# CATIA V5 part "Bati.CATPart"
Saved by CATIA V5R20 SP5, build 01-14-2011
Part number: Bati
Bounding box of the stored display mesh (mm): x -250 to 20, y -10 to 10, z -15 to 130
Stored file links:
  D:\thinkmotion-MPB\Dropbox\IAO\IAO_2010\iao\IAO OK\IAO_2010_1447_melguidj\Catia_1447_melguidj\Bati.CATPart
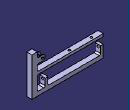
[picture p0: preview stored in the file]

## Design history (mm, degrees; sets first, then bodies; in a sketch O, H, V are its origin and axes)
Body1 (main body)
  Plane1: stored without definition
  Sketch1 on zx-plane, origin (0, 0, 0), H (-1, 0, 0), V (0, 0, 1)
    line L1 (0, 130) -> (-20, 130)
    point P1 (0, 130)
    line L2 (-20, 130) -> (-20, -15)
    line L3 (-20, -15) -> (250, -15)
    point P4 (250, -15)
    line L4 (0, 130) -> (0, 115)
    line L5 (5, 0) -> (25, 0)
    line L6 (30, 5) -> (30, 30)
    line L7 (30, 30) -> (40, 30)
    line L8 (40, 30) -> (40, 5)
    point P7 (40, 0)
    line L9 (45, 0) -> (235, 0)
    line L10 (240, 5) -> (240, 30)
    point P8 (240, 30)
    line L11 (240, 30) -> (250, 30)
    line L12 (250, 30) -> (250, -15)
    point P10 (250, -15)
    reference intersected line E1 through (0, 0) direction (-1, 0) from Plane1
    point P11 (0, 110)
    line L13 (5, 110) -> (20, 110)
    line L14 (20, 90) -> (5, 90)
    line L15 (0, 85) -> (0, 70)
    circle A1 centre (20, 100) radius 4
    point P12 (20, 100)
    arc A2 centre (45, 5) radius 5 from (40, 5) to (45, 0) ccw
    arc A3 centre (25, 5) radius 5 from (30, 5) to (25, 0) cw
    arc A4 centre (5, 5) radius 5 from (5, 0) to (0, 5) cw
    arc A5 centre (235, 5) radius 5 from (240, 5) to (235, 0) cw
    arc A6 centre (5, 85) radius 5 from (5, 90) to (0, 85) ccw
    arc A7 centre (5, 115) radius 5 from (5, 110) to (0, 115) cw
    line L16 (5, 65) -> (250, 65)
    line L17 (250, 65) -> (250, 55)
    line L18 (250, 55) -> (5, 55)
    line L19 (0, 50) -> (0, 5)
    arc A8 centre (5, 50) radius 5 from (0, 50) to (5, 55) cw
    arc A9 centre (5, 70) radius 5 from (5, 65) to (0, 70) cw
    arc A10 centre (20, 100) radius 10 from (20, 90) to (20, 110) ccw
    distance L9 L3 = 15
    distance L10 L12 = 10
    length L7 = 10
    distance L8 L10 = 200
    distance L6 L4 = 30
    length L1 = 20
    distance L1 E1 = 130
    distance L14 L5 = 90
    distance P12 L13 = 10
    radius A1 = 4
    distance L7 L9 = 30
    radius A2 = 5
    radius A3 = 5
    radius A4 = 5
    radius A5 = 5
    radius A6 = 5
    radius A7 = 5
    length L17 = 10
    distance L18 L5 = 55
    radius A8 = 5
    radius A9 = 5
    distance P12 L4 = 20
    coincidence: P1 V, P7 L5, P8 L7, P10 P4, L5 H, L4 L15, L8 P7, L9 P7, L13 P11, L4 P11, L17 L12, L15 L19
    horizontal: L1 H, L3 H, L5 H, L7 H, L9 H, L11 H, L13 H, L14 H, L16 H, L18 H
    vertical: L2 V, L4 V, L6 V, L8 V, L10 V, L12 V, L15 V, L17 V, L19 V
    tangency: A2 L8, A2 L9, A3 L6, A3 L5, A4 L5, A4 L15, A5 L10, A5 L9, A6 L14, A6 L15, A7 L13, A7 L4, A8 L19, A8 L18, A9 L16, A9 L15, A10 L13, A10 L14
  Pad1: profile Sketch1, direction (0, 1, 0), length 10, mirrored extent
  Sketch2 on face of Pad1 from Sketch1.L12, origin (-250, 0, 0), H (0, -1, 0), V (0, 0, 1)
    circle A1 centre (0, 23) radius 4
    point P1 (0, 23)
    reference projected line E1 (10, 30) -> (-10, 30) from edge [face of Pad1 from Sketch1.L11 | face of Pad1 from Sketch1.L12]
    radius A1 = 4
    distance E1 P1 = 7
    coincidence: P1 V
  Pocket1: profile Sketch2, direction (1, 0, 0), up to face of Pad1 from Sketch1.L6
  Sketch3 on face of Pad1 from Sketch1.L13, origin (0, 0, 110), H (1, 0, 0), V (0, 1, 0)
    line L1 (-53.7186, 7) -> (-5, 7)
    line L2 (-5, 7) -> (-5, -7)
    line L3 (-5, -7) -> (-53.7186, -7)
    line L4 (-53.7186, -7) -> (-53.7186, 7)
    reference projected line E1 (-20, 10) -> (-5, 10) from edge [face of Pad1 from Sketch1.L13 | end face of Pad1]
    reference projected line E2 (-20, -10) -> (-5, -10) from edge [start face of Pad1 | face of Pad1 from Sketch1.L13]
    reference projected line E3 (-5, -10) -> (-5, 10) from edge [face of Pad1 from Sketch1.A7 | face of Pad1 from Sketch1.L13]
    distance L1 E1 = 3
    distance L3 E2 = 3
    horizontal: L1 H, L3 H
    vertical: L2 V, L4 V
    coincidence: L2 E3
  Pocket2: profile Sketch3, direction (0, 0, -1), up to face of Pad1 from Sketch1.L14
  Sketch4 on face of Pad1 from Sketch1.L16, origin (0, 0, 65), H (1, 0, 0), V (0, 1, 0)
    circle A1 centre (-215, 0) radius 4
    point P1 (-215, 0)
    reference projected line E1 (-250, -10) -> (-250, 10) from edge [face of Pad1 from Sketch1.L16 | face of Pad1 from Sketch1.L17]
    radius A1 = 4
    distance P1 E1 = 35
    coincidence: P1 H
  Pocket3: profile Sketch4, direction (0, 0, -1), through (limit type 6)
  Sketch5 on zx-plane, origin (0, 0, 0), H (-1, 0, 0), V (0, 0, 1)
    point P1 (20, 100)
    reference projected arc E1 centre (20, 100) radius 10 from (20, 90) to (20, 110) ccw from edge [face of Pad1 from Sketch1.A10 | end face of Pad1]
    concentricity: E1 P1
  Sketch6 on face of Pad1 from Sketch1.L16, origin (-109.5895, -1.7809, 65), H (1, 0, 0), V (0, 1, 0)
    point P1 (-21.9505, 1.7809)
    reference projected circle E1 centre (-105.4105, 1.7809) radius 4 from edge [face of Pad1 from Sketch1.L16 | face of Pocket3 from Sketch4.A1]
    reference projected line E2 (-140.4105, 11.7809) -> (104.5895, 11.7809) from edge [face of Pad1 from Sketch1.L16 | end face of Pad1]
    distance P1 E1 = 79.46
    distance P1 E2 = 10
  Hole1: placed by Sketch6, at (-131.54, 0, 65) direction (0, 0, -1), diameter 8, through (limit type 6)
  Sketch7 on face of Pad1 from Sketch1.L16, origin (0, 0, 65), H (1, 0, 0), V (0, 1, 0)
    line L1 (94.8259, 0) -> (-324.6614, 0)
    point P1 (94.8259, 0)
    coincidence: P1 H
    horizontal: L1 H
